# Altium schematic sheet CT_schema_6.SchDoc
size 221 x 258 mm
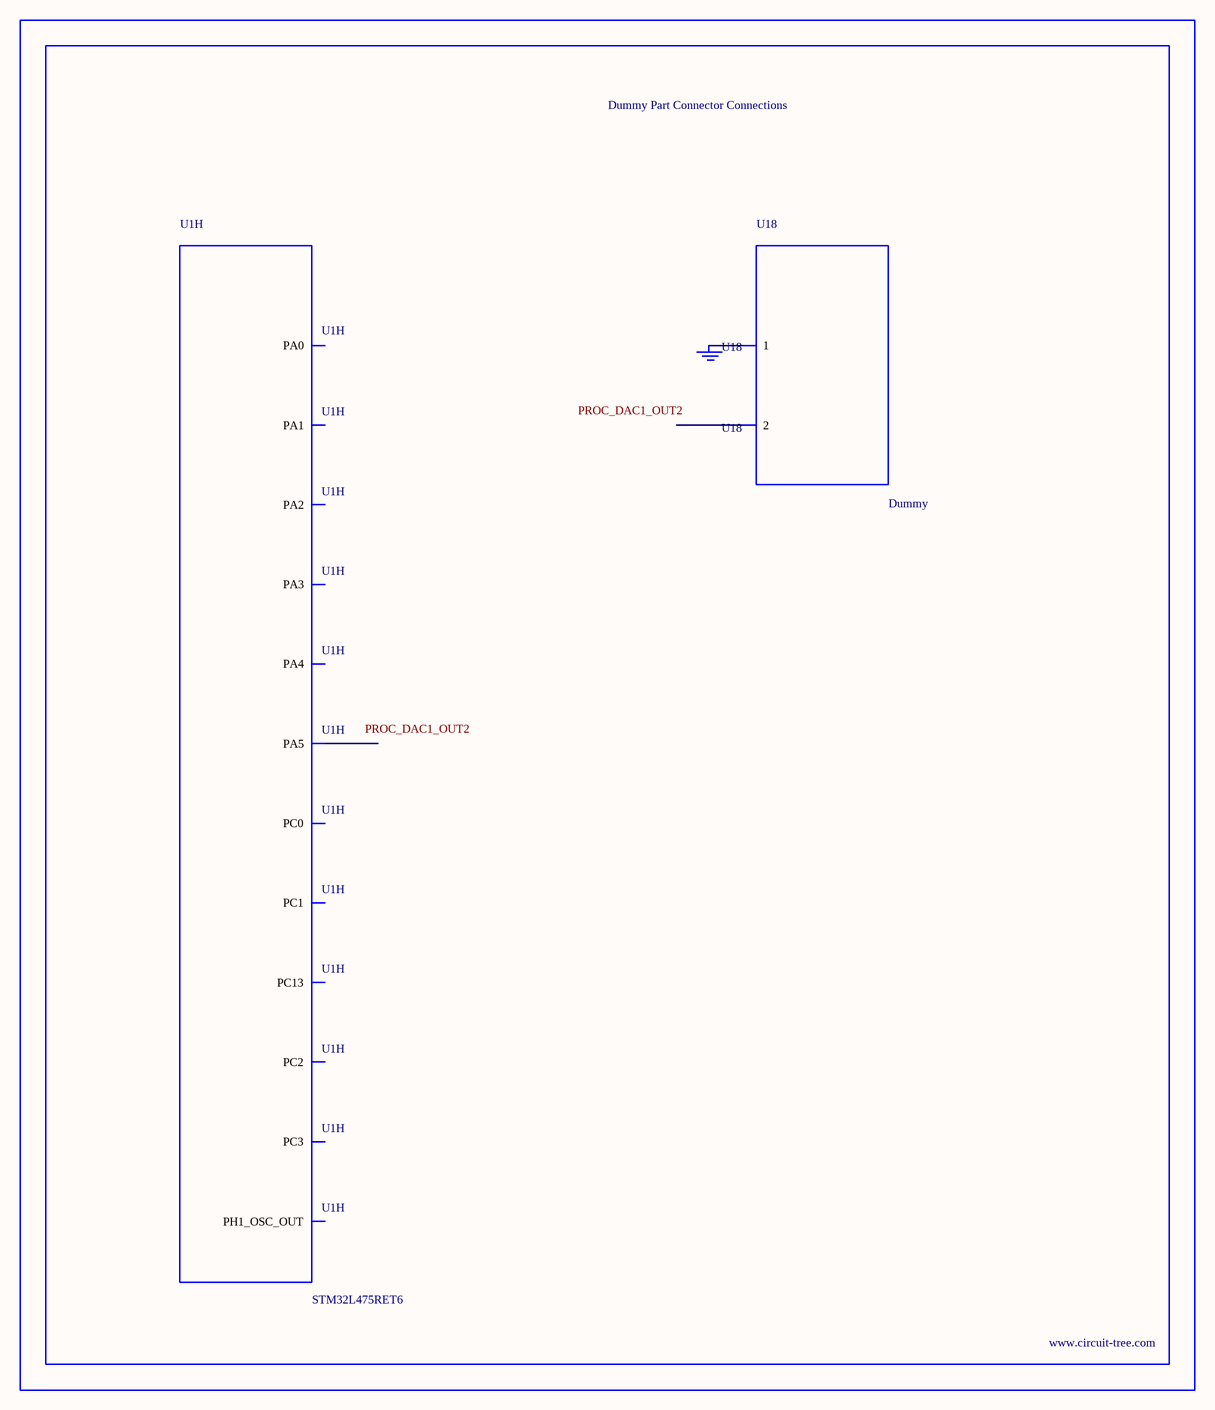
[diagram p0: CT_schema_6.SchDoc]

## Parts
BORDER5  (no value)
GND_INSTANCE_5_0  (no value)
U1  STM32L475RET6  [LQFP64]  (part H of 8)
U18  Dummy  [DUMMY_PACKAGE_138]

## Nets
NetGND_INSTANCE_5_0_0: GND_INSTANCE_5_0.0(GND) U18.1

Not connected (* = marked no-connect by the designer): U1 2(PC13) 6(PH1_OSC_OUT) 8(PC0) 9(PC1) 10(PC2) 11(PC3) 14(PA0) 15(PA1) 16(PA2) 17(PA3) 20(PA4) 21(PA5); U18 2

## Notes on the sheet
- Labels drawn without touching a wire or pin: PROC_DAC1_OUT2

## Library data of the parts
BORDER5 = BORDER_PAGE5
GND_INSTANCE_5_0 = GND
